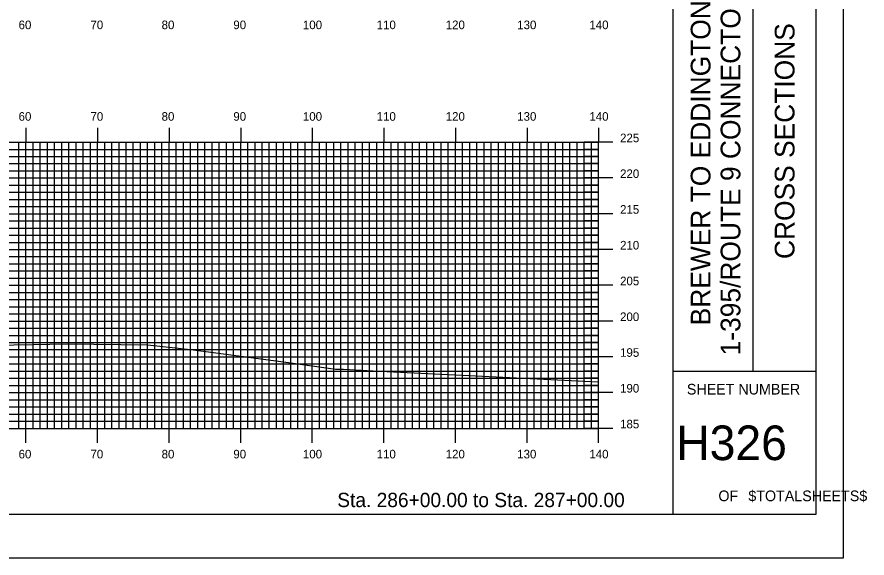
# Model space of a CAD drawing. Extents: x 1812554 to 1812897, y 442591 to 442811.
# Drawn here: x 1812778.7 to 1812897.4, y 442590.5 to 442666.2 of the extents above; entities that cross this region are included whole.
import ezdxf

# ---------------------------------------------------------------- set-up
doc = ezdxf.new("R2010")
doc.units = 0
for name, color, linetype in [('BORDER', 7, 'Continuous'), ('H_V ANNOTATION', 7, 'Continuous'), ('MAJOR', 7, 'Continuous'), ('MINOR', 7, 'Continuous'), ('PLOT BOUNDARY', 7, 'Continuous'), ('S_Roadway_Centerline', 7, 'Continuous')]:
    doc.layers.add(name, color=color, linetype=linetype)

msp = doc.modelspace()

# ---------------------------------------------------------------- linework, layer by layer
at = {"layer": 'BORDER'}
for p, q in [((1812870.34, 442596.67), (1812870.34, 442806.67)), ((1812881.52, 442616.67), (1812881.52, 442686.67)), ((1812870.34, 442616.67), (1812890.34, 442616.67))]:
    msp.add_line(p, q, dxfattribs=at)
msp.add_lwpolyline([(1812570.34, 442596.67), (1812890.34, 442596.67), (1812890.34, 442806.67), (1812570.34, 442806.67)], close=True, dxfattribs=at)
at = {"layer": 'MAJOR'}
for p, q in [((1812779.94, 442650.67), (1812779.94, 442648.67)), ((1812789.94, 442650.67), (1812789.94, 442648.67)), ((1812799.94, 442650.67), (1812799.94, 442648.67)), ((1812809.94, 442650.67), (1812809.94, 442648.67)), ((1812819.94, 442650.67), (1812819.94, 442648.67)), ((1812829.94, 442650.67), (1812829.94, 442648.67)), ((1812839.94, 442650.67), (1812839.94, 442648.67)), ((1812849.94, 442650.67), (1812849.94, 442648.67)), ((1812859.94, 442650.67), (1812859.94, 442648.67)), ((1812579.94, 442648.67), (1812859.94, 442648.67)), ((1812579.94, 442648.67), (1812859.94, 442648.67)), ((1812779.94, 442608.67), (1812779.94, 442648.67)), ((1812789.94, 442608.67), (1812789.94, 442648.67)), ((1812799.94, 442608.67), (1812799.94, 442648.67)), ((1812809.94, 442608.67), (1812809.94, 442648.67)), ((1812819.94, 442608.67), (1812819.94, 442648.67)), ((1812829.94, 442608.67), (1812829.94, 442648.67)), ((1812839.94, 442608.67), (1812839.94, 442648.67)), ((1812849.94, 442608.67), (1812849.94, 442648.67)), ((1812861.95, 442648.67), (1812857.94, 442648.67)), ((1812859.94, 442608.67), (1812859.94, 442648.67)), ((1812859.94, 442608.67), (1812859.94, 442648.67)), ((1812579.94, 442643.67), (1812859.94, 442643.67)), ((1812861.95, 442643.67), (1812857.94, 442643.67)), ((1812579.94, 442638.67), (1812859.94, 442638.67)), ((1812861.95, 442638.67), (1812857.94, 442638.67)), ((1812579.94, 442633.67), (1812859.94, 442633.67)), ((1812861.95, 442633.67), (1812857.94, 442633.67)), ((1812579.94, 442628.67), (1812859.94, 442628.67)), ((1812861.95, 442628.67), (1812857.94, 442628.67)), ((1812579.94, 442623.67), (1812859.94, 442623.67)), ((1812861.95, 442623.67), (1812857.94, 442623.67)), ((1812579.94, 442618.67), (1812859.94, 442618.67)), ((1812861.95, 442618.67), (1812857.94, 442618.67)), ((1812579.94, 442613.67), (1812859.94, 442613.67)), ((1812861.95, 442613.67), (1812857.94, 442613.67)), ((1812579.94, 442608.67), (1812859.94, 442608.67)), ((1812579.94, 442608.67), (1812859.94, 442608.67)), ((1812779.94, 442606.66), (1812779.94, 442608.67)), ((1812789.94, 442606.66), (1812789.94, 442608.67)), ((1812799.94, 442606.66), (1812799.94, 442608.67)), ((1812809.94, 442606.66), (1812809.94, 442608.67)), ((1812819.94, 442606.66), (1812819.94, 442608.67)), ((1812829.94, 442606.66), (1812829.94, 442608.67)), ((1812839.94, 442606.66), (1812839.94, 442608.67)), ((1812849.94, 442606.66), (1812849.94, 442608.67)), ((1812861.95, 442608.67), (1812857.94, 442608.67)), ((1812859.94, 442606.66), (1812859.94, 442608.67))]:
    msp.add_line(p, q, dxfattribs=at)
at = {"layer": 'MINOR'}
for p, q in [((1812778.94, 442608.67), (1812778.94, 442648.67)), ((1812780.94, 442608.67), (1812780.94, 442648.67)), ((1812781.94, 442608.67), (1812781.94, 442648.67)), ((1812782.94, 442608.67), (1812782.94, 442648.67)), ((1812783.94, 442608.67), (1812783.94, 442648.67)), ((1812784.94, 442608.67), (1812784.94, 442648.67)), ((1812785.94, 442608.67), (1812785.94, 442648.67)), ((1812786.94, 442608.67), (1812786.94, 442648.67)), ((1812787.94, 442608.67), (1812787.94, 442648.67)), ((1812788.94, 442608.67), (1812788.94, 442648.67)), ((1812790.94, 442608.67), (1812790.94, 442648.67)), ((1812791.94, 442608.67), (1812791.94, 442648.67)), ((1812792.94, 442608.67), (1812792.94, 442648.67)), ((1812793.94, 442608.67), (1812793.94, 442648.67)), ((1812794.94, 442608.67), (1812794.94, 442648.67)), ((1812795.94, 442608.67), (1812795.94, 442648.67)), ((1812796.94, 442608.67), (1812796.94, 442648.67)), ((1812797.94, 442608.67), (1812797.94, 442648.67)), ((1812798.94, 442608.67), (1812798.94, 442648.67)), ((1812800.94, 442608.67), (1812800.94, 442648.67)), ((1812801.94, 442608.67), (1812801.94, 442648.67)), ((1812802.94, 442608.67), (1812802.94, 442648.67)), ((1812803.94, 442608.67), (1812803.94, 442648.67)), ((1812804.94, 442608.67), (1812804.94, 442648.67)), ((1812805.94, 442608.67), (1812805.94, 442648.67)), ((1812806.94, 442608.67), (1812806.94, 442648.67)), ((1812807.94, 442608.67), (1812807.94, 442648.67)), ((1812808.94, 442608.67), (1812808.94, 442648.67)), ((1812810.94, 442608.67), (1812810.94, 442648.67)), ((1812811.94, 442608.67), (1812811.94, 442648.67)), ((1812812.94, 442608.67), (1812812.94, 442648.67)), ((1812813.94, 442608.67), (1812813.94, 442648.67)), ((1812814.94, 442608.67), (1812814.94, 442648.67)), ((1812815.94, 442608.67), (1812815.94, 442648.67)), ((1812816.94, 442608.67), (1812816.94, 442648.67)), ((1812817.94, 442608.67), (1812817.94, 442648.67)), ((1812818.94, 442608.67), (1812818.94, 442648.67)), ((1812820.94, 442608.67), (1812820.94, 442648.67)), ((1812821.94, 442608.67), (1812821.94, 442648.67)), ((1812822.94, 442608.67), (1812822.94, 442648.67)), ((1812823.94, 442608.67), (1812823.94, 442648.67)), ((1812824.94, 442608.67), (1812824.94, 442648.67)), ((1812825.94, 442608.67), (1812825.94, 442648.67)), ((1812826.94, 442608.67), (1812826.94, 442648.67)), ((1812827.94, 442608.67), (1812827.94, 442648.67)), ((1812828.94, 442608.67), (1812828.94, 442648.67)), ((1812830.94, 442608.67), (1812830.94, 442648.67)), ((1812831.94, 442608.67), (1812831.94, 442648.67)), ((1812832.94, 442608.67), (1812832.94, 442648.67)), ((1812833.94, 442608.67), (1812833.94, 442648.67)), ((1812834.94, 442608.67), (1812834.94, 442648.67)), ((1812835.94, 442608.67), (1812835.94, 442648.67)), ((1812836.94, 442608.67), (1812836.94, 442648.67)), ((1812837.94, 442608.67), (1812837.94, 442648.67)), ((1812838.94, 442608.67), (1812838.94, 442648.67)), ((1812840.94, 442608.67), (1812840.94, 442648.67)), ((1812841.94, 442608.67), (1812841.94, 442648.67)), ((1812842.94, 442608.67), (1812842.94, 442648.67)), ((1812843.94, 442608.67), (1812843.94, 442648.67)), ((1812844.94, 442608.67), (1812844.94, 442648.67)), ((1812845.94, 442608.67), (1812845.94, 442648.67)), ((1812846.94, 442608.67), (1812846.94, 442648.67)), ((1812847.94, 442608.67), (1812847.94, 442648.67)), ((1812848.94, 442608.67), (1812848.94, 442648.67)), ((1812850.94, 442608.67), (1812850.94, 442648.67)), ((1812851.94, 442608.67), (1812851.94, 442648.67)), ((1812852.94, 442608.67), (1812852.94, 442648.67)), ((1812853.94, 442608.67), (1812853.94, 442648.67)), ((1812854.94, 442608.67), (1812854.94, 442648.67)), ((1812855.94, 442608.67), (1812855.94, 442648.67)), ((1812856.94, 442608.67), (1812856.94, 442648.67)), ((1812857.94, 442608.67), (1812857.94, 442648.67)), ((1812858.94, 442608.67), (1812858.94, 442648.67)), ((1812579.94, 442647.67), (1812859.94, 442647.67)), ((1812859.94, 442647.67), (1812857.94, 442647.67)), ((1812579.94, 442646.67), (1812859.94, 442646.67)), ((1812859.94, 442646.67), (1812857.94, 442646.67)), ((1812579.94, 442645.67), (1812859.94, 442645.67)), ((1812859.94, 442645.67), (1812857.94, 442645.67)), ((1812579.94, 442644.67), (1812859.94, 442644.67)), ((1812859.94, 442644.67), (1812857.94, 442644.67)), ((1812579.94, 442642.67), (1812859.94, 442642.67)), ((1812859.94, 442642.67), (1812857.94, 442642.67)), ((1812579.94, 442641.67), (1812859.94, 442641.67)), ((1812859.94, 442641.67), (1812857.94, 442641.67)), ((1812579.94, 442640.67), (1812859.94, 442640.67)), ((1812859.94, 442640.67), (1812857.94, 442640.67)), ((1812579.94, 442639.67), (1812859.94, 442639.67)), ((1812859.94, 442639.67), (1812857.94, 442639.67)), ((1812579.94, 442637.67), (1812859.94, 442637.67)), ((1812859.94, 442637.67), (1812857.94, 442637.67)), ((1812579.94, 442636.67), (1812859.94, 442636.67)), ((1812859.94, 442636.67), (1812857.94, 442636.67)), ((1812579.94, 442635.67), (1812859.94, 442635.67)), ((1812859.94, 442635.67), (1812857.94, 442635.67)), ((1812579.94, 442634.67), (1812859.94, 442634.67)), ((1812859.94, 442634.67), (1812857.94, 442634.67)), ((1812579.94, 442632.67), (1812859.94, 442632.67)), ((1812579.94, 442631.67), (1812859.94, 442631.67)), ((1812859.94, 442632.67), (1812857.94, 442632.67)), ((1812859.94, 442631.67), (1812857.94, 442631.67)), ((1812579.94, 442630.67), (1812859.94, 442630.67)), ((1812859.94, 442630.67), (1812857.94, 442630.67)), ((1812579.94, 442629.67), (1812859.94, 442629.67)), ((1812859.94, 442629.67), (1812857.94, 442629.67)), ((1812579.94, 442627.67), (1812859.94, 442627.67)), ((1812859.94, 442627.67), (1812857.94, 442627.67)), ((1812579.94, 442626.67), (1812859.94, 442626.67)), ((1812859.94, 442626.67), (1812857.94, 442626.67)), ((1812579.94, 442625.67), (1812859.94, 442625.67)), ((1812579.94, 442624.67), (1812859.94, 442624.67)), ((1812859.94, 442625.67), (1812857.94, 442625.67)), ((1812859.94, 442624.67), (1812857.94, 442624.67)), ((1812579.94, 442622.67), (1812859.94, 442622.67)), ((1812859.94, 442622.67), (1812857.94, 442622.67)), ((1812579.94, 442621.67), (1812859.94, 442621.67)), ((1812859.94, 442621.67), (1812857.94, 442621.67)), ((1812579.94, 442620.67), (1812859.94, 442620.67)), ((1812859.94, 442620.67), (1812857.94, 442620.67)), ((1812579.94, 442619.67), (1812859.94, 442619.67)), ((1812859.94, 442619.67), (1812857.94, 442619.67)), ((1812579.94, 442617.67), (1812859.94, 442617.67)), ((1812859.94, 442617.67), (1812857.94, 442617.67)), ((1812579.94, 442616.67), (1812859.94, 442616.67)), ((1812859.94, 442616.67), (1812857.94, 442616.67)), ((1812579.94, 442615.67), (1812859.94, 442615.67)), ((1812859.94, 442615.67), (1812857.94, 442615.67)), ((1812579.94, 442614.67), (1812859.94, 442614.67)), ((1812859.94, 442614.67), (1812857.94, 442614.67)), ((1812579.94, 442612.67), (1812859.94, 442612.67)), ((1812859.94, 442612.67), (1812857.94, 442612.67)), ((1812579.94, 442611.67), (1812859.94, 442611.67)), ((1812859.94, 442611.67), (1812857.94, 442611.67)), ((1812579.94, 442610.67), (1812859.94, 442610.67)), ((1812859.94, 442610.67), (1812857.94, 442610.67)), ((1812579.94, 442609.67), (1812859.94, 442609.67)), ((1812859.94, 442609.67), (1812857.94, 442609.67))]:
    msp.add_line(p, q, dxfattribs=at)
at = {"layer": 'PLOT BOUNDARY'}
msp.add_lwpolyline([(1812554.16, 442590.55), (1812894.16, 442590.55), (1812894.16, 442810.55), (1812554.16, 442810.55)], close=True, dxfattribs=at)
at = {"layer": 'S_Roadway_Centerline'}
msp.add_lwpolyline([(1812770.37, 442620.21), (1812780.84, 442620.41), (1812785.68, 442620.49), (1812796.92, 442620.33), (1812803.36, 442619.66), (1812816.93, 442617.83), (1812823.18, 442616.96), (1812824.32, 442616.94), (1812828.45, 442616.73), (1812859.94, 442615.18)], dxfattribs=at)

# ---------------------------------------------------------------- texts
at = {"layer": 'BORDER'}
for s, p in [('1-395/ROUTE 9 CONNECTOR', (1812879.75, 442618.87)), ('BREWER TO EDDINGTON', (1812875.57, 442623.07)), ('CROSS SECTIONS', (1812887.31, 442632.34))]:
    msp.add_text(s, height=2.7557, rotation=90, dxfattribs=at).set_placement(p)
for s, height, p in [('SHEET NUMBER', 1.4905, (1812872.27, 442613.4)), ('H326', 4.839, (1812870.78, 442604.23)), ('OF', 1.491, (1812876.68, 442598.49)), ('$TOTALSHEETS$', 1.4905, (1812880.86, 442598.49))]:
    msp.add_text(s, height=height, dxfattribs=at).set_placement(p)
at = {"layer": 'H_V ANNOTATION'}
for s, height, p in [('60', 1.2, (1812778.91, 442664.47)), ('70', 1.2, (1812788.95, 442664.47)), ('80', 1.2, (1812798.89, 442664.47)), ('90', 1.2, (1812808.91, 442664.47)), ('100', 1.2, (1812818.63, 442664.47)), ('110', 1.2, (1812828.93, 442664.47)), ('120', 1.2, (1812838.58, 442664.47)), ('130', 1.2, (1812848.57, 442664.47)), ('140', 1.2, (1812858.65, 442664.47)), ('60', 1.2, (1812778.91, 442651.67)), ('70', 1.2, (1812788.95, 442651.67)), ('80', 1.2, (1812798.89, 442651.67)), ('90', 1.2, (1812808.91, 442651.67)), ('100', 1.2, (1812818.63, 442651.67)), ('110', 1.2, (1812828.93, 442651.67)), ('120', 1.2, (1812838.58, 442651.67)), ('130', 1.2, (1812848.57, 442651.67)), ('140', 1.2, (1812858.65, 442651.67)), ('225', 1.2, (1812862.94, 442648.67)), ('220', 1.2, (1812862.94, 442643.67)), ('215', 1.2, (1812862.94, 442638.67)), ('210', 1.2, (1812862.94, 442633.67)), ('205', 1.2, (1812862.94, 442628.67)), ('200', 1.2, (1812862.94, 442623.67)), ('195', 1.2, (1812862.94, 442618.67)), ('190', 1.2, (1812862.94, 442613.67)), ('185', 1.2, (1812862.94, 442608.67)), ('60', 1.2, (1812778.91, 442604.47)), ('70', 1.2, (1812788.95, 442604.47)), ('80', 1.2, (1812798.89, 442604.47)), ('90', 1.2, (1812808.91, 442604.47)), ('100', 1.2, (1812818.63, 442604.47)), ('110', 1.2, (1812828.93, 442604.47)), ('120', 1.2, (1812838.58, 442604.47)), ('130', 1.2, (1812848.57, 442604.47)), ('140', 1.2, (1812858.65, 442604.47)), ('Sta. 286+00.00 to Sta. 287+00.00', 2.0004, (1812823.43, 442597.66))]:
    msp.add_text(s, height=height, dxfattribs=at).set_placement(p)

doc.saveas('drawing.dxf')
